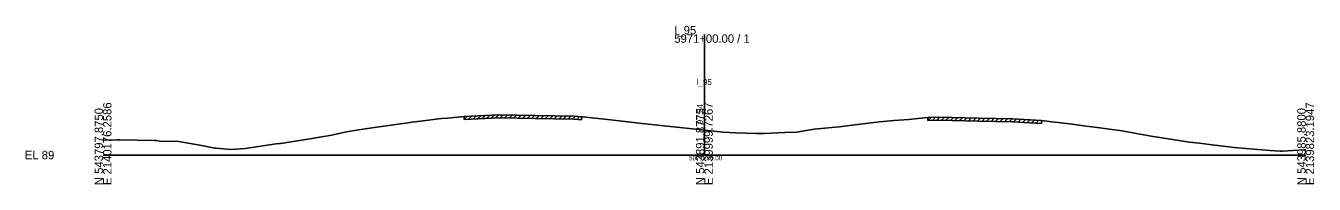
# Model space of a CAD drawing. Extents: x -12534 to 3403, y -1332 to 21983.
# Drawn here: x -25.7 to 402.8, y 5990.3 to 6042.9 of the extents above; entities that cross this region are included whole.
import ezdxf

# ---------------------------------------------------------------- set-up
doc = ezdxf.new("R2010")
doc.units = 0
for name, color, linetype in [('RD_GPK_XS_Cell', 7, 'Continuous'), ('RD_XS_ExGround', 7, 'Continuous'), ('RD_XS_ExPaveRet', 7, 'Continuous'), ('RD_XS_TX_Baseline', 7, 'Continuous'), ('RD_XS_TX_Elev_EX', 7, 'Continuous'), ('RD_XS_TX_Station', 7, 'Continuous')]:
    doc.layers.add(name, color=color, linetype=linetype)

msp = doc.modelspace()

# ---------------------------------------------------------------- linework, layer by layer
at = {"layer": 'RD_GPK_XS_Cell'}
for p, q in [((200, 6000), (200, 6040.08)), ((0, 6000), (200, 6000)), ((200, 6000), (400, 6000))]:
    msp.add_line(p, q, dxfattribs=at)
at = {"layer": 'RD_XS_ExGround'}
msp.add_lwpolyline([(0, 6004.91), (4.75, 6005.04), (5.62, 6005.05), (17.11, 6004.87), (17.77, 6004.8), (18.8, 6004.6), (25.17, 6004.52), (33.47, 6003.05), (37.11, 6002.3), (37.55, 6002.27), (42.74, 6001.8), (47.32, 6002.13), (57.59, 6003.67), (58.73, 6003.81), (59.11, 6003.88), (61.09, 6004.17), (69.6, 6005.46), (72.71, 6006), (75.49, 6006.49), (75.94, 6006.57), (80.56, 6007.56), (82.88, 6008.04), (88.7, 6008.88), (91.12, 6009.24), (102.21, 6010.85), (102.66, 6010.91), (105.54, 6011.26), (112.57, 6012.1), (114.6, 6012.29), (118.96, 6012.68), (120.06, 6012.78), (131.63, 6013.36), (143.75, 6013.09), (156.65, 6012.87), (159.15, 6012.73), (159.55, 6012.68), (164.66, 6012.12), (167.78, 6011.79), (173.64, 6011.16), (179.25, 6010.48), (182.41, 6010.17), (187.64, 6009.63), (199.17, 6008.33), (200, 6008.24), (206.21, 6007.58), (210.4, 6007.36), (217.27, 6007.18), (219.88, 6007.2), (226.78, 6007.43), (230.63, 6007.6), (236.49, 6008.57), (237.66, 6008.66), (244.87, 6009.32), (251.84, 6010.26), (254.54, 6010.59), (258.19, 6011.05), (259.45, 6011.17), (263.01, 6011.48), (268, 6011.84), (273.1, 6012.33), (274.35, 6012.45), (277.97, 6012.59), (291.16, 6012.27), (302.65, 6012.01), (312.14, 6011.48), (315.57, 6011.07), (317.79, 6010.84), (322.34, 6010.26), (327.04, 6009.62), (329.88, 6009.26), (337.24, 6008.23), (338.21, 6008.09), (338.8, 6007.99), (348.61, 6006.27), (355.68, 6005.11), (359.21, 6004.56), (361.36, 6004.28), (364.71, 6003.94), (368.05, 6003.46), (376.24, 6002.47), (388.1, 6001.52), (391.66, 6001.24), (392.23, 6001.26), (399.47, 6001.68), (400, 6001.75)], dxfattribs=at)
at = {"layer": 'RD_XS_ExPaveRet'}
for p, q in [((120.06, 6011.78), (121.12, 6012.84)), ((120.06, 6011.78), (120.06, 6012.78)), ((120.06, 6011.78), (131.63, 6012.36)), ((121.56, 6011.86), (122.62, 6012.91)), ((123.06, 6011.93), (124.12, 6012.99)), ((124.56, 6012.01), (125.62, 6013.06)), ((126.06, 6012.08), (127.12, 6013.13)), ((127.56, 6012.16), (128.62, 6013.21)), ((129.06, 6012.23), (130.12, 6013.28)), ((130.56, 6012.31), (131.62, 6013.36)), ((131.63, 6012.36), (143.75, 6012.09)), ((132.06, 6012.35), (133.04, 6013.33)), ((133.56, 6012.32), (134.54, 6013.29)), ((135.06, 6012.28), (136.04, 6013.26)), ((136.56, 6012.25), (137.54, 6013.23)), ((138.06, 6012.22), (139.04, 6013.19)), ((139.56, 6012.18), (140.54, 6013.16)), ((141.06, 6012.15), (142.04, 6013.13)), ((142.56, 6012.11), (143.54, 6013.09)), ((144.06, 6012.08), (145.05, 6013.07)), ((145.56, 6012.06), (146.55, 6013.04)), ((147.06, 6012.03), (148.05, 6013.02)), ((148.56, 6012.01), (149.55, 6012.99)), ((150.06, 6011.98), (151.05, 6012.97)), ((151.56, 6011.96), (152.55, 6012.94)), ((153.06, 6011.93), (154.05, 6012.92)), ((154.56, 6011.91), (155.55, 6012.89)), ((156.06, 6011.88), (157.03, 6012.85)), ((157.56, 6011.82), (158.51, 6012.77)), ((159.15, 6012.73), (159.15, 6011.73)), ((274.35, 6011.45), (275.39, 6012.49)), ((274.35, 6011.45), (274.35, 6012.45)), ((275.85, 6011.51), (276.89, 6012.54)), ((277.35, 6011.56), (278.36, 6012.58)), ((278.85, 6011.56), (279.83, 6012.54)), ((280.35, 6011.53), (281.33, 6012.5)), ((281.85, 6011.49), (282.83, 6012.47)), ((283.35, 6011.45), (284.33, 6012.43)), ((284.85, 6011.42), (285.83, 6012.39)), ((286.35, 6011.38), (287.33, 6012.36)), ((287.85, 6011.35), (288.83, 6012.32)), ((143.75, 6012.09), (156.65, 6011.87)), ((156.65, 6011.87), (159.15, 6011.73)), ((274.35, 6011.45), (277.97, 6011.59)), ((277.97, 6011.59), (291.16, 6011.27)), ((289.35, 6011.31), (290.33, 6012.29)), ((290.85, 6011.27), (291.83, 6012.25)), ((291.16, 6011.27), (302.65, 6011.01)), ((292.35, 6011.24), (293.33, 6012.22)), ((293.85, 6011.21), (294.83, 6012.18)), ((295.35, 6011.17), (296.33, 6012.15)), ((296.85, 6011.14), (297.83, 6012.12)), ((298.35, 6011.11), (299.33, 6012.08)), ((299.85, 6011.07), (300.83, 6012.05)), ((301.35, 6011.04), (302.33, 6012.02)), ((302.65, 6011.01), (312.14, 6010.48)), ((302.85, 6011), (303.8, 6011.95)), ((304.35, 6010.92), (305.3, 6011.86)), ((305.85, 6010.83), (306.8, 6011.78)), ((307.35, 6010.75), (308.3, 6011.7)), ((308.85, 6010.67), (309.8, 6011.61)), ((310.35, 6010.58), (311.3, 6011.53)), ((312.14, 6011.48), (312.14, 6010.48))]:
    msp.add_line(p, q, dxfattribs=at)

# ---------------------------------------------------------------- texts
at = {"layer": 'RD_GPK_XS_Cell'}
for s, p in [('I_95', (190, 6040.08)), ('5971+00.00 / 1', (190, 6037.28)), ('EL 89', (-26, 5998.6))]:
    msp.add_text(s, height=2.8, dxfattribs=at).set_placement(p)
for s, p in [('E 2140176.2586', (2.8, 5990)), ('E 2139999.7267', (202.8, 5990)), ('E 2139823.1947', (402.8, 5990)), ('N 543797.8750', (0, 5990)), ('N 543891.8775', (200, 5990)), ('N 543985.8800', (400, 5990))]:
    msp.add_text(s, height=2.8, rotation=90, dxfattribs=at).set_placement(p)
at = {"layer": 'RD_XS_TX_Baseline'}
msp.add_text('I_95', height=2, dxfattribs=at).set_placement((197.28, 6023.24))
at = {"layer": 'RD_XS_TX_Elev_EX'}
msp.add_text('97.24', height=2, rotation=90, dxfattribs=at).set_placement((199.5, 6010.24))
at = {"layer": 'RD_XS_TX_Station'}
msp.add_text('5971+00.00', height=1.5, dxfattribs=at).set_placement((194.93, 5998.24))

doc.saveas('drawing.dxf')
